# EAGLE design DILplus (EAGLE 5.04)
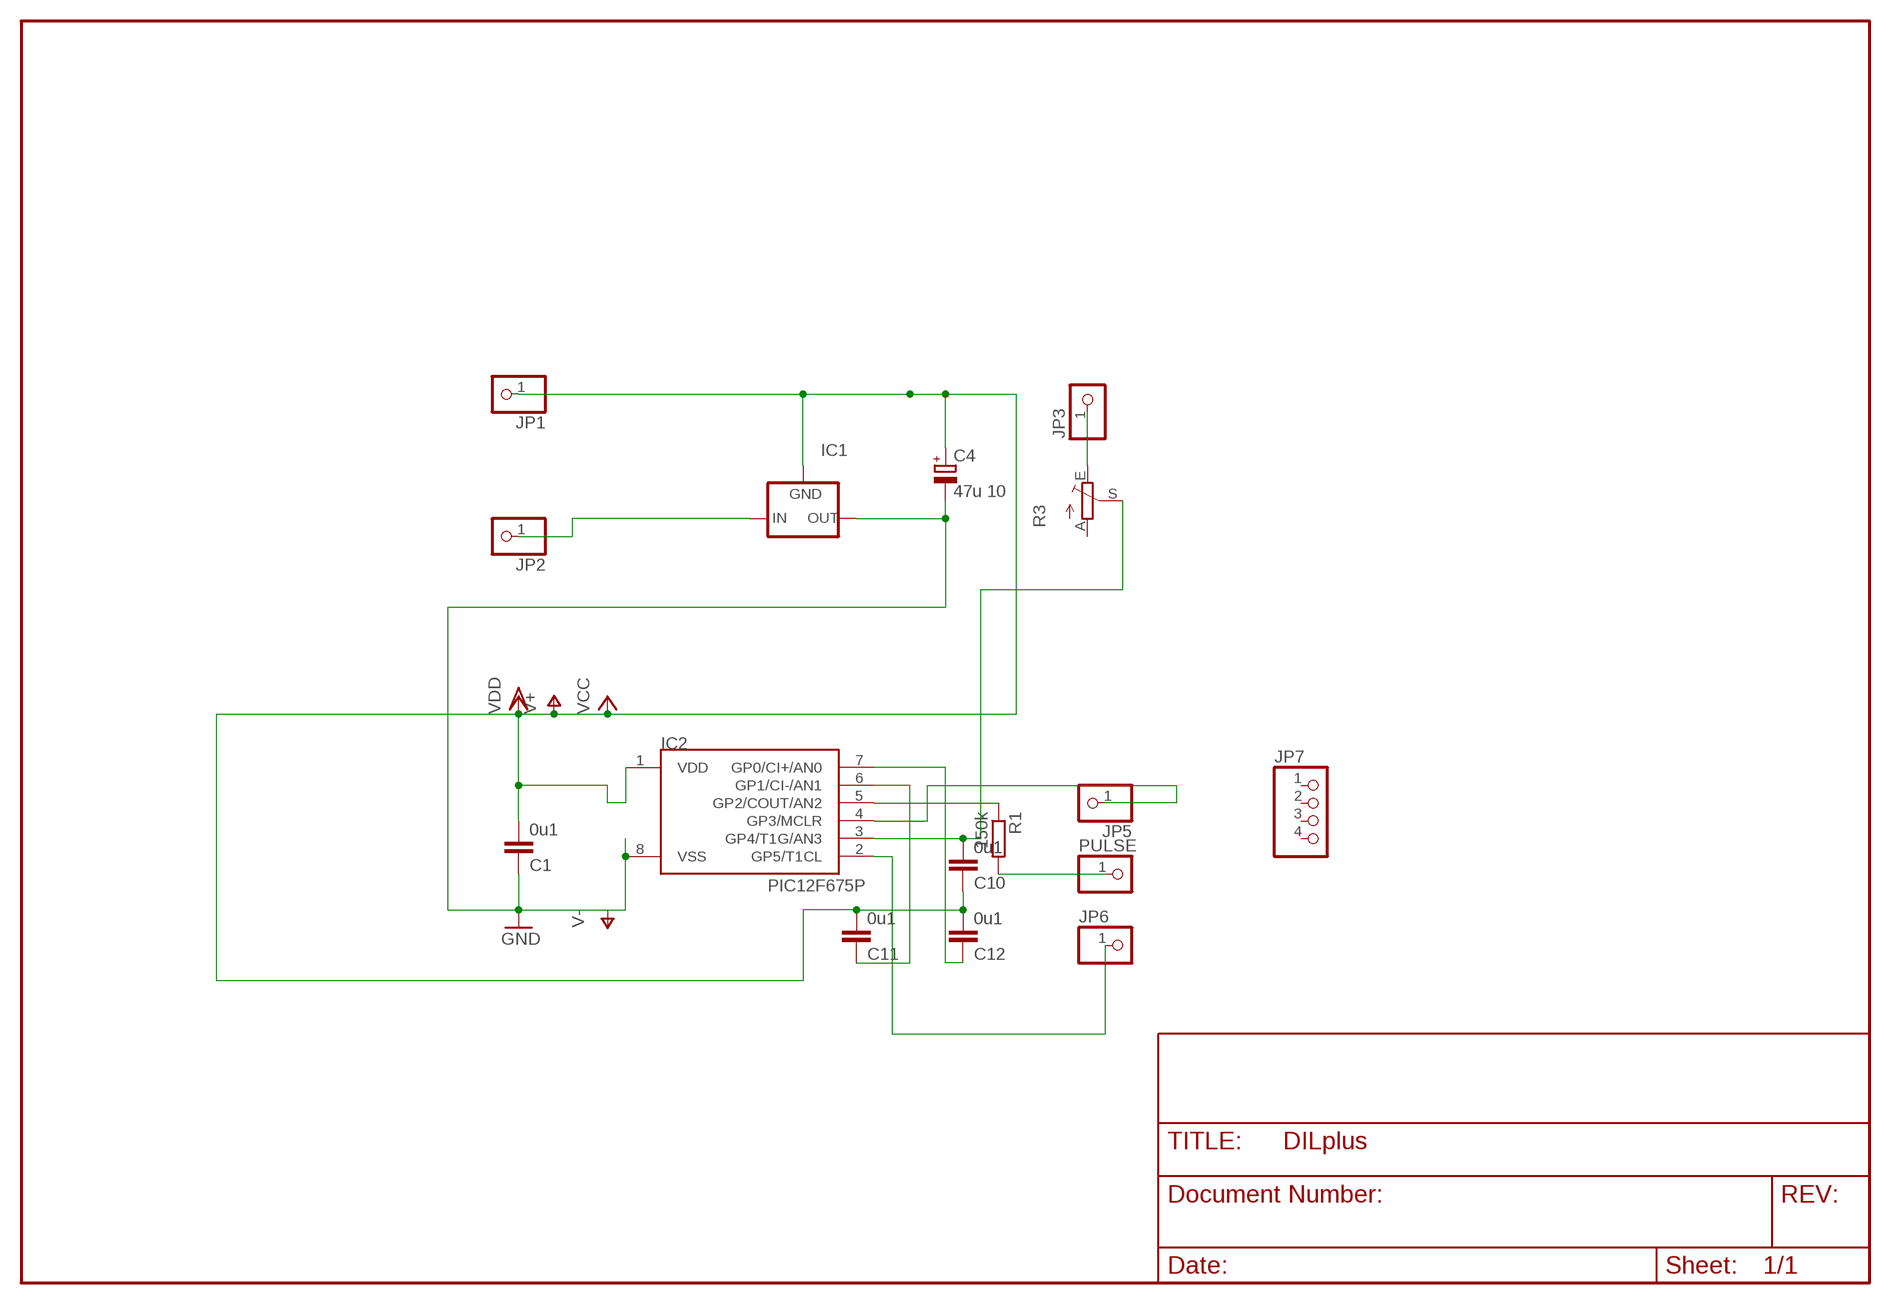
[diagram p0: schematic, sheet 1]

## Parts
C1  0u1  C-EUC1206  [C1206]
C4  47u 10  CPOL-EUE2.5-6  [E2,5-6]
C10  0u1  C-EUC1206  [C1206]
C11  0u1  C-EUC1206  [C1206]
C12  0u1  C-EUC1206  [C1206]
IC1  79LXX  [79LXX]
IC2  PIC12F675P  [DIL8]
JP1  PINHD-1X1  [1X01]
JP2  PINHD-1X1  [1X01]
JP3  PINHD-1X1  [1X01]
JP5  PINHD-1X1  [1X01]
JP6  PINHD-1X1  [1X01]
JP7  PINHD-1X4  [1X04]
PULSE  PINHD-1X1  [1X01]
R1  150k  R-EU_0204/2V  [0204V]
R3  TRIM_EU-CA6V  [CA6V]

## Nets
GND: C1.1 C4.- IC1.OUT IC2.8(VSS)
N$1: JP3.1 R3.E
N$2: PULSE.1 R1.2
N$3: IC2.4(GP3/MCLR) JP5.1
N$4: IC2.2(GP5/T1CL) JP6.1
N$5: IC2.5(GP2/COUT/AN2) R1.1
N$8: IC1.IN JP2.1
N$12: C10.2 IC2.3(GP4/T1G/AN3) R3.S
N$13: C12.1 IC2.7(GP0/CI+/AN0)
N$15: C11.1 IC2.6(GP1/CI-/AN1)
V+: C1.2 C4.+ C10.1 C11.2 C12.2 IC1.GND IC2.1(VDD) JP1.1 ; supply symbol labelled VCC, VDD
Unconnected: JP7.1 JP7.2 JP7.3 JP7.4 R3.A

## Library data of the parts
C1 C10-C12 = rcl:C-EU: CAPACITOR, European symbol
C4 = rcl:CPOL-EU: POLARIZED CAPACITOR, European symbol
IC1 = v-reg:79LXX: VOLTAGE REGULATOR
IC2 = microchip-3:PIC12F6*: uPC nW 1k Program Flash memory 2x Timer Comparator 10b A/D converter/ 4xIN
JP1-JP3 JP5 JP6 PULSE = pinhead:PINHD-1X1: PIN HEADER
JP7 = pinhead(2):PINHD-1X4: PIN HEADER
R1 = rcl:R-EU_: RESISTOR, European symbol
R3 = pot:TRIM_EU-: POTENTIOMETER

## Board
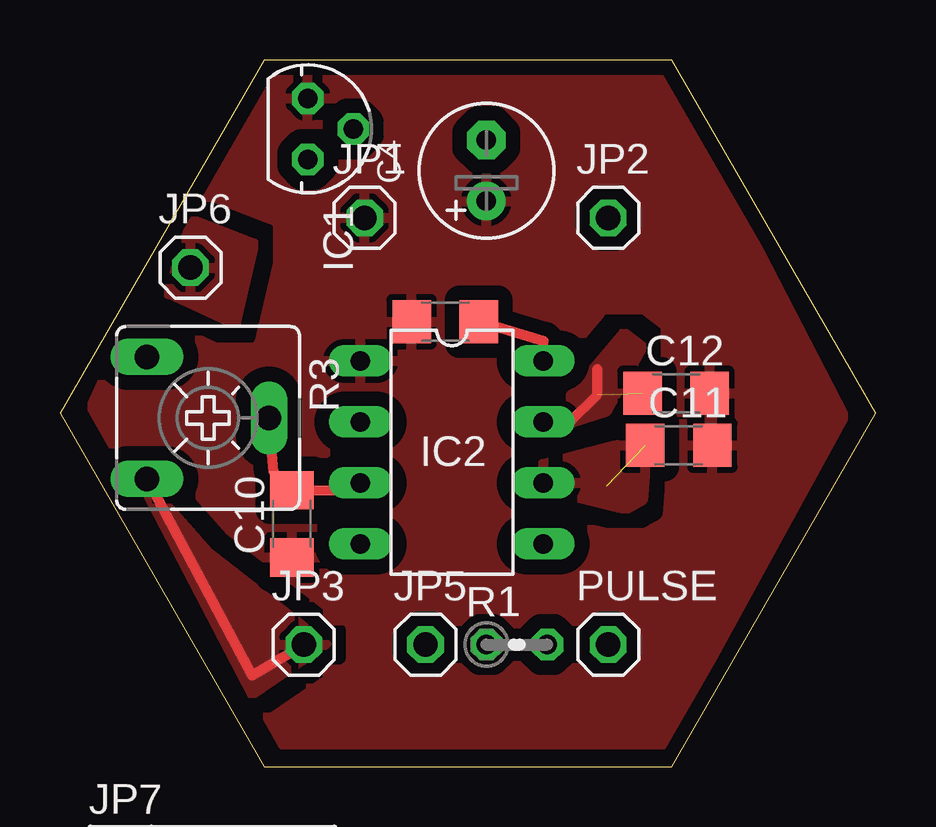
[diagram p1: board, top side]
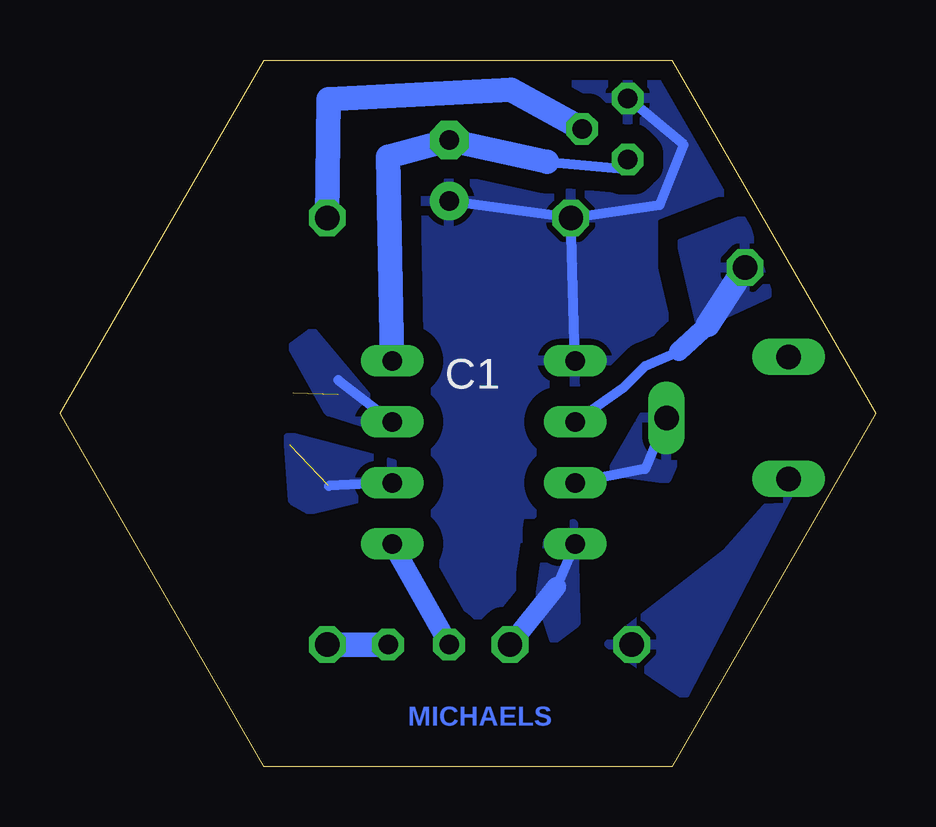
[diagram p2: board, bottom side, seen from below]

Size 34 x 29.44 mm. Coordinates in mm from the lower left corner, seen from the top.
Outline: 8.5,0 25.5,0 34,14.72 25.5,29.44 8.5,29.44 0,14.72 8.5,0
Copper layers (1*16): Top 0.035mm / dielectric 1.5mm / Bottom 0.035mm
Design rules "default *": minimum track width 10mil, minimum drill 24mil, track to track 8mil, track to pad 8mil, pad to pad 8mil, via to via 8mil, smd to smd 8mil, copper to edge 10mil, drill to drill 8mil, minimum pad ring 10mil, minimum via ring 8mil, stop-mask expansion 4mil, vias tented up to drill 0mil, thermal gap 10mil

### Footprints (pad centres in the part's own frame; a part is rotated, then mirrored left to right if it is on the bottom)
C1206 = smd 1.6 x 1.8: 1 -1.4,0; 2 1.4,0
E2,5-6 = drill 0.813 pad 1.6 round: + -1.27,0 | drill 0.813 pad 1.6 octagon: - 1.27,0
79LXX = drill 0.813 octagon: GND -1.27,0; IN 0,1.905; OUT 1.27,0
DIL8 = drill 0.813 long: 1 -3.81,-3.81; 2 -1.27,-3.81; 3 1.27,-3.81; 4 3.81,-3.81; 5 3.81,3.81; 6 1.27,3.81; 7 -1.27,3.81; 8 -3.81,3.81
1X01 = drill 1.016 octagon: 1 0,0
1X04 = drill 1.016 square: 1 -3.81,0 | drill 1.016 octagon: 2 -1.27,0; 3 1.27,0; 4 3.81,0
0204V = drill 0.813 octagon: 1 -1.27,0; 2 1.27,0
CA6V = drill 1.016 long: A -2.54,-2.54; E 2.54,-2.54; S 0,2.54

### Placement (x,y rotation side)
C1  16.06,18.54 180 top
C4  17.78,24.83 90 top
C10  9.67,10.11 90 top
C11  25.8,13.39 0 top
C12  25.68,15.55 0 top
IC1  10.33,26.57 270 top
IC2  16.34,13.09 270 top
JP1  12.7,22.86 0 top
JP2  22.86,22.86 0 top
JP3  10.16,5.08 0 top
JP5  15.24,5.08 0 top
JP6  5.44,20.79 0 top
JP7  not placed on the board
PULSE  22.86,5.08 0 top
R1  19.05,5.08 0 top
R3  6.17,14.53 270 top

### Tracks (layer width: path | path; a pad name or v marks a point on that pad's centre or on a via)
GND
  Top 0.406: C1.1 20.16,17.73 IC2.8
  Bottom 0.406: IC1.OUT 10.5,24.9 13.7,25.2
  Bottom 1.016: 13.7,25.2 C4.- 20.32,25.4 IC2.8
N$1
  Top 0.406: JP3.1 8,3.8 R3.E
  pour Top (isolate 0.61): 3.1,12.4 8,3 11.1,5.1 6.2,8.9
  pour Bottom (isolate 0.61): 3.1,12.4 8,3 11.1,5.1 6.2,8.9
N$2
  Bottom 1.016: R1.2 PULSE.1
N$3
  Bottom 0.406: IC2.4 13.3,7.49
  Bottom 0.813: 13.3,7.49 JP5.1
  pour Bottom (isolate 0.61): 12.6,10.1 13.6,9.8 14,7.1 13.4,5.3 12.5,6
N$4
  Bottom 0.406: IC2.2 10.5,15.8 9.6,16.7 8.2,17.3
  Bottom 0.813: 8.2,17.3 7,18.4
  Bottom 1.016: 7,18.4 JP6.1
  pour Bottom (isolate 0.61): 5.2,21.8 5.5,22.8 8.1,21.8 7.3,18.4 4.5,19.7
  pour Top (isolate 0.61): 5.2,21.8 5.5,22.8 8.1,21.8 7.3,18.4 4.5,19.7
N$5
  Bottom 0.813: R1.1 IC2.5
N$8
  Bottom 1.016: IC1.IN 15.2,28.2 22.8,27.8 JP2.1
N$12
  Top 0.406: R3.S 8.91,12.27 C10.2 12.22,11.51
  Bottom 0.406: IC2.3 9.6,12.4 R3.S
  pour Bottom (isolate 0.61): 9.5,14.9 11,12.3 8.7,12 7.9,13.8
N$13  (1 unrouted)
  Top 0.406: IC2.7 21.26,14.36 22.4,15.5 22.4,16.56
  Bottom 0.406: IC2.7 22.4,16.1
  pour Top (isolate 0.61): 20.9,14.2 22.8,14.8 24.3,17.5 23.5,18.1 20.3,14.3
  pour Bottom (isolate 0.406): 20.9,14.2 22.8,14.8 24.3,17.5 23.5,18.1 20.3,14.3
N$15  (1 unrouted)
  Bottom 0.406: IC2.6 22.8,11.7
  pour Top (isolate 0.61, rank 2): 20.1,12.6 24.3,13.7 24.5,13.7 24.3,11.1 23.6,10.7 20.7,11.4
  pour Bottom (isolate 0.61, rank 2): 20.1,12.6 24.3,13.7 24.5,13.7 24.3,11.1 23.6,10.7 20.7,11.4
V+
  Bottom 0.406: IC1.GND 8,25.9 9,23.4 JP1.1 | JP1.1 C4.+ | IC2.1 JP1.1
  pour Top (isolate 0.61, rank 3): 7.72,29.04 25.3,28.9 32.7,14.6 25.2,0.9 9.3,0.9 1.3,15
  pour Bottom (isolate 0.813, rank 3): 8.32,29.14 27.1,29 32.7,14.6 25.2,0.9 9.3,0.9 1.3,15

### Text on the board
Bottom: MICHAELS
